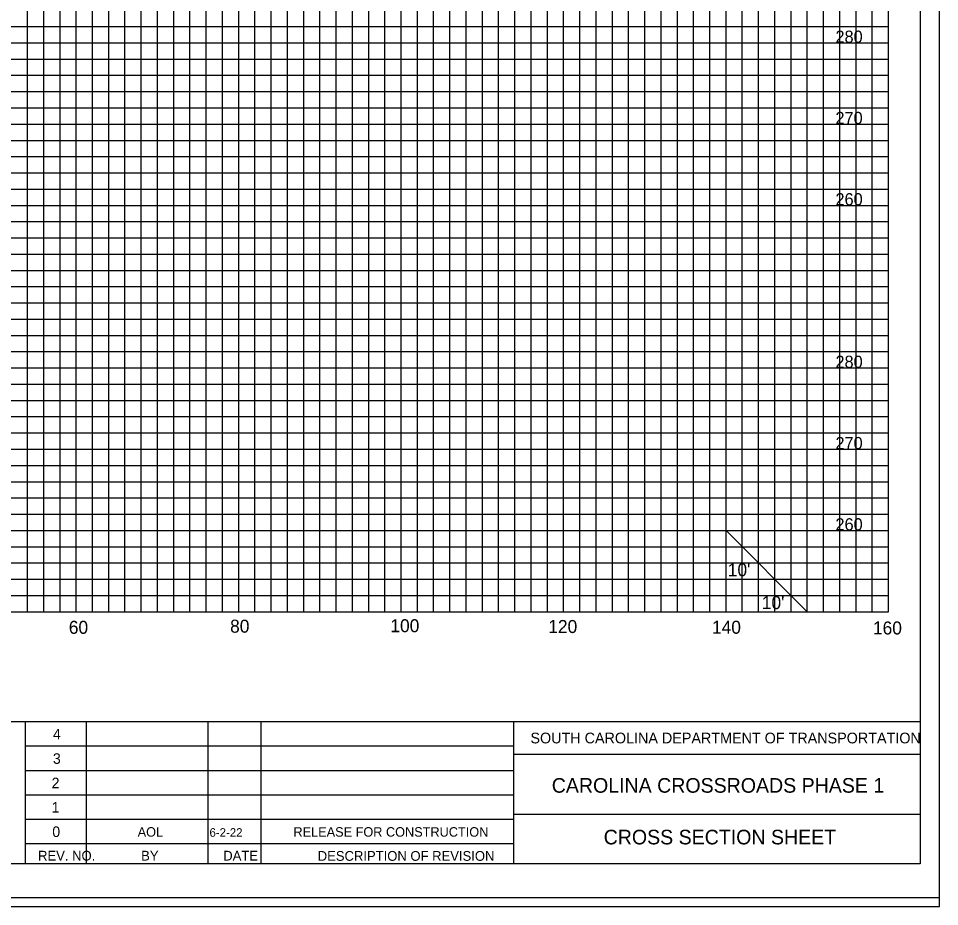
# Model space of a CAD drawing. Extents: x 967 to 1326, y 964 to 3704.
# Drawn here: x 1212.9 to 1326.3, y 1803.7 to 1913 of the extents above; entities that cross this region are included whole.
import ezdxf

# ---------------------------------------------------------------- set-up
doc = ezdxf.new("R2010")
doc.units = 0
for name, color, linetype in [('Default', 7, 'Continuous'), ('RD_SHT_Bndy', 7, 'Continuous'), ('RD_SHT_IplotShp', 7, 'Continuous'), ('RD_SHT_Misc1', 7, 'Continuous'), ('RD_SHT_MjGrid', 7, 'Continuous'), ('RD_SHT_MnGrid', 7, 'Continuous'), ('RD_SHT_TX', 7, 'Continuous'), ('RD_XS_TX_Station', 7, 'Continuous')]:
    doc.layers.add(name, color=color, linetype=linetype)

msp = doc.modelspace()

# ---------------------------------------------------------------- linework, layer by layer
at = {"layer": 'RD_SHT_Bndy'}
for p, q in [((1323.89, 2018.46), (1323.89, 1808.98)), ((996.11, 1826.49), (1323.89, 1826.49)), ((1213.76, 1808.94), (1213.76, 1826.49)), ((1221.26, 1808.95), (1221.26, 1826.48)), ((1236.26, 1808.95), (1236.26, 1826.48)), ((1242.76, 1808.95), (1242.76, 1826.48)), ((1273.88, 1808.98), (1273.88, 1826.49)), ((1213.76, 1823.48), (1273.88, 1823.48)), ((1323.93, 1822.43), (1273.88, 1822.43)), ((1213.76, 1820.48), (1273.88, 1820.48)), ((1213.76, 1817.48), (1273.88, 1817.48)), ((1213.76, 1814.48), (1273.88, 1814.48)), ((1323.89, 1815.04), (1273.88, 1815.04)), ((1213.76, 1811.48), (1273.88, 1811.48)), ((1323.89, 1808.98), (996.11, 1808.98))]:
    msp.add_line(p, q, dxfattribs=at)
at = {"layer": 'RD_SHT_IplotShp'}
for points in [[(967.41, 1803.72), (1326.28, 1803.72), (1326.28, 2023.72), (967.41, 2023.72)], [(988.52, 1804.84), (1326.28, 1804.84), (1326.28, 2022.6), (988.52, 2022.6)]]:
    msp.add_lwpolyline(points, close=True, dxfattribs=at)
at = {"layer": 'RD_SHT_MjGrid'}
for p, q in [((1220, 1840), (1220, 2010)), ((1230, 1840), (1230, 2010)), ((1240, 1840), (1240, 2010)), ((1250, 1840), (1250, 2010)), ((1260, 1840), (1260, 2010)), ((1270, 1840), (1270, 2010)), ((1280, 1840), (1280, 2010)), ((1290, 1840), (1290, 2010)), ((1300, 1840), (1300, 2010)), ((1310, 1840), (1310, 2010)), ((1320, 1840), (1320, 2010)), ((1000, 1910), (1320, 1910)), ((1000, 1900), (1320, 1900)), ((1000, 1890), (1320, 1890)), ((1000, 1880), (1320, 1880)), ((1000, 1870), (1320, 1870)), ((1000, 1860), (1320, 1860)), ((1000, 1850), (1320, 1850)), ((1000, 1840), (1320, 1840))]:
    msp.add_line(p, q, dxfattribs=at)
at = {"layer": 'RD_SHT_MnGrid'}
for p, q in [((1214, 1840), (1214, 2010)), ((1216, 1840), (1216, 2010)), ((1218, 1840), (1218, 2010)), ((1222, 1840), (1222, 2010)), ((1224, 1840), (1224, 2010)), ((1226, 1840), (1226, 2010)), ((1228, 1840), (1228, 2010)), ((1232, 1840), (1232, 2010)), ((1234, 1840), (1234, 2010)), ((1236, 1840), (1236, 2010)), ((1238, 1840), (1238, 2010)), ((1242, 1840), (1242, 2010)), ((1244, 1840), (1244, 2010)), ((1246, 1840), (1246, 2010)), ((1248, 1840), (1248, 2010)), ((1252, 1840), (1252, 2010)), ((1254, 1840), (1254, 2010)), ((1256, 1840), (1256, 2010)), ((1258, 1840), (1258, 2010)), ((1262, 1840), (1262, 2010)), ((1264, 1840), (1264, 2010)), ((1266, 1840), (1266, 2010)), ((1268, 1840), (1268, 2010)), ((1272, 1840), (1272, 2010)), ((1274, 1840), (1274, 2010)), ((1276, 1840), (1276, 2010)), ((1278, 1840), (1278, 2010)), ((1282, 1840), (1282, 2010)), ((1284, 1840), (1284, 2010)), ((1286, 1840), (1286, 2010)), ((1288, 1840), (1288, 2010)), ((1292, 1840), (1292, 2010)), ((1294, 1840), (1294, 2010)), ((1296, 1840), (1296, 2010)), ((1298, 1840), (1298, 2010)), ((1302, 1840), (1302, 2010)), ((1304, 1840), (1304, 2010)), ((1306, 1840), (1306, 2010)), ((1308, 1840), (1308, 2010)), ((1312, 1840), (1312, 2010)), ((1314, 1840), (1314, 2010)), ((1316, 1840), (1316, 2010)), ((1318, 1840), (1318, 2010)), ((1000, 1912), (1320, 1912)), ((1000, 1908), (1320, 1908)), ((1000, 1906), (1320, 1906)), ((1000, 1904), (1320, 1904)), ((1000, 1902), (1320, 1902)), ((1000, 1898), (1320, 1898)), ((1000, 1896), (1320, 1896)), ((1000, 1894), (1320, 1894)), ((1000, 1892), (1320, 1892)), ((1000, 1888), (1320, 1888)), ((1000, 1886), (1320, 1886)), ((1000, 1884), (1320, 1884)), ((1000, 1882), (1320, 1882)), ((1000, 1878), (1320, 1878)), ((1000, 1876), (1320, 1876)), ((1000, 1874), (1320, 1874)), ((1000, 1872), (1320, 1872)), ((1000, 1868), (1320, 1868)), ((1000, 1866), (1320, 1866)), ((1000, 1864), (1320, 1864)), ((1000, 1862), (1320, 1862)), ((1000, 1858), (1320, 1858)), ((1000, 1856), (1320, 1856)), ((1000, 1854), (1320, 1854)), ((1000, 1852), (1320, 1852)), ((1000, 1848), (1320, 1848)), ((1000, 1846), (1320, 1846)), ((1000, 1844), (1320, 1844)), ((1000, 1842), (1320, 1842))]:
    msp.add_line(p, q, dxfattribs=at)
at = {"layer": 'RD_SHT_TX'}
msp.add_line((1300, 1850), (1310, 1840), dxfattribs=at)
at = {"layer": 'RD_XS_TX_Station'}
msp.add_lwpolyline([(967.41, 1803.72), (1326.28, 1803.72), (1326.28, 2023.72), (967.41, 2023.72)], close=True, dxfattribs=at)

# ---------------------------------------------------------------- texts
at = {"layer": 'Default'}
for s, p in [('280', (1313.47, 1910)), ('270', (1313.47, 1900)), ('260', (1313.47, 1890)), ('280', (1313.47, 1870)), ('270', (1313.47, 1860)), ('260', (1313.47, 1850))]:
    msp.add_text(s, height=1.5, dxfattribs=at).set_placement(p)
at = {"layer": 'RD_SHT_Misc1'}
for s, height, p in [('AOL', 1.17, (1227.56, 1812.32)), ('6-2-22', 1.053, (1236.4, 1812.31)), ('RELEASE FOR CONSTRUCTION', 1.17, (1246.74, 1812.32))]:
    msp.add_text(s, height=height, dxfattribs=at).set_placement(p)
at = {"layer": 'RD_SHT_TX'}
for s, height, p in [("10'", 1.6, (1300.21, 1844.36)), ("10'", 1.6, (1304.4, 1840.32)), ('60', 1.6, (1219.08, 1837.28)), ('80', 1.6, (1238.94, 1837.42)), ('100', 1.6, (1258.67, 1837.48)), ('120', 1.6, (1278.11, 1837.38)), ('140', 1.6, (1298.26, 1837.29)), ('160', 1.6, (1318.08, 1837.2)), ('4', 1.3, (1217.13, 1824.28)), ('SOUTH CAROLINA DEPARTMENT OF TRANSPORTATION', 1.32, (1275.92, 1823.8)), ('3', 1.3, (1217.13, 1821.28)), ('2', 1.3, (1216.97, 1818.28)), ('1', 1.3, (1216.97, 1815.28)), ('0', 1.3, (1217.05, 1812.28)), ('REV. NO.', 1.2, (1215.3, 1809.38)), ('BY', 1.2, (1227.99, 1809.38)), ('DATE', 1.2, (1238.1, 1809.38)), ('DESCRIPTION OF REVISION', 1.2, (1249.73, 1809.35))]:
    msp.add_text(s, height=height, dxfattribs=at).set_placement(p)
for s, p in [('CAROLINA CROSSROADS PHASE 1', (1278.54, 1817.73)), ('CROSS SECTION SHEET', (1284.93, 1811.37))]:
    msp.add_text(s, height=1.8, rotation=0, dxfattribs=at).set_placement(p)

doc.saveas('drawing.dxf')
